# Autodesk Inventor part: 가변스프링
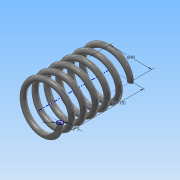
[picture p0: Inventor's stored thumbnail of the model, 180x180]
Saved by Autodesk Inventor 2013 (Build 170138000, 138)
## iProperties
Created: 2016-08
Part Number: 가변스프링
Material: 스테인리스강
Document SubType Name: Modeling
Designer: Administrator
Density: 8.08 g/cm^3
Mass: 117.905 g
Surface Area: 118.251 cm^2
Volume: 14.5922 cm^3
Author: Administrator
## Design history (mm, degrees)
sketch "스케치1"
  geometry: L1 (0, 0)-(20, 0); L2 (20, 0)-(20, 67.25); L3 (20, 67.25)-(0, 67.25); L4 (0, 67.25)-(0, 0); C1 r 2.5 at (20, 0)
  constraints: 8 end point, 2 parallel, 1 centre point, 1 coincident, 1 horizontal, 1 perpendicular
  dimensions: "d0" = 67.25 distance of L1.end L2.end (derived); "d2" = 40 diameter of L2 L4; "d3" = 5 diameter of C1
feature "코일1" pitch "d4" = 10; turns "d6" = 6; dims "d5" = 67.25 (= d0), "d7" = 0, angle "d8" = 90 deg, angle "d9" = 90 deg, "d10" = 0, "d11" = 0
sketch "스케치2"
  geometry: L1 (-22.5, 0)-(-17.5, 0) reference; L2 (-22.5, 0)-(-17.5, 0) reference; 1 further point
  constraints: 2 horizontal alignment
extrude "돌출1" cut sketch "스케치2" distance "d12" = 10; taper "d13" = 0 deg
node "작업 평면1"
sketch "스케치3"
  geometry: L1 (22.5, 0)-(17.5, 0) reference; 1 further point
  constraints: 1 horizontal alignment
extrude "돌출2" cut sketch "스케치3" distance "d14" = 10; taper "d15" = 0 deg
node "솔리드1"
node "절단 모서리 투영1"
node "절단 모서리 투영2"
node "절단 모서리 투영3"
